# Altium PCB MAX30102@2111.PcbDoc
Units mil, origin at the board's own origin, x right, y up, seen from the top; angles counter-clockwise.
Board outline 354.33 x 295.28 mil, 2 copper layers (Top Layer, Bottom Layer); 8 components, 6 nets, 42 pads, 10 vias.
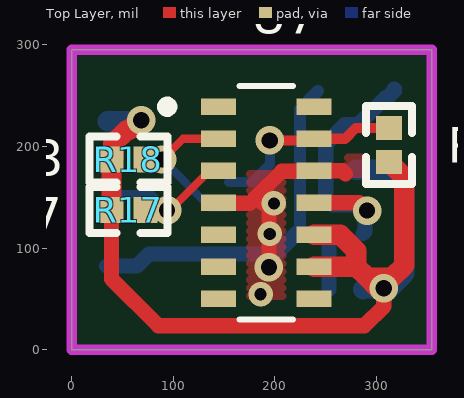
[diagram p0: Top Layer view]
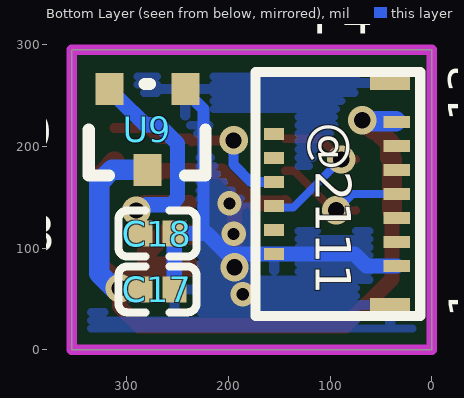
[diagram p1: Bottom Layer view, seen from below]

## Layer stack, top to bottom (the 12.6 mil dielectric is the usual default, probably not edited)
Top Solder: solder mask 0.4, Solder Resist, Dk 3.5
Top Layer: signal copper 1.4
Dielectric 1: dielectric 12.6, FR-4, Dk 4.8
Bottom Layer: signal copper 1.4
Bottom Solder: solder mask 0.4, Solder Resist, Dk 3.5

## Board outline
0,0 354.33,0 354.33,295.28 0,295.28

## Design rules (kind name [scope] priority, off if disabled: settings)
Clearance Clearance_1 [InPolygon] p1: gap=10 ignorepadtopadclearanceinfootprint=FALSE
Clearance [All] p2: gap=6 ignorepadtopadclearanceinfootprint=FALSE
ComponentClearance [All] p1 off: gap=10 collisioncheckmode=3 verticalgap=10 showdistances=FALSE
DiffPairsRouting [All] p1: maxlimit=10 minlimit=7 mostfreqgap=8 toplayer_minwidth=6 toplayer_maxwidth=15 toplayer_prefwidth=8 bottomlayer_minwidth=6 bottomlayer_maxwidth=15 bottomlayer_prefwidth=8 maxuncoupledlength=500
MinimumSolderMaskSliver [All] p1 off: minsoldermaskwidth=10
PolygonConnect PolygonConnect_1 [IsVia] p1: connectstyle=Direct reliefconductorwidth=10 reliefentries=4 polygonreliefangle="90 Angle" airgapwidth=10
PolygonConnect [All] p2: connectstyle=Relief reliefconductorwidth=10 reliefentries=4 polygonreliefangle="90 Angle" airgapwidth=10
RoutingVias [All] p1: holewidth=16 width=28 viastyle="Through Hole" minholewidth=12 minwidth=24 maxholewidth=28 maxwidth=50
SilkToSilkClearance [All] p1 off: silktosilkclearance=10
SilkToSolderMaskClearance [IsPad] p1 off: minsilkscreentomaskgap=10 clearancetoexposedcopper=TRUE
SolderMaskExpansion [All] p1: expansion=4 istentingtop=FALSE
Width [All] p1: maxlimit=100 minlimit=6 preferedwidth=10
25 further rules are at their usual default settings.

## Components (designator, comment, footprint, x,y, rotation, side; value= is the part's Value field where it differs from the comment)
C17 "100nF" 0402_C 286.76,59.42 r90 bottom
C18 "100nF" 0402_C 286.76,114.33 r90 bottom
P4 "13PIN_0.3mm" FFC/FPC-13(6+7)-P0.3 34.34,153.17 r90 bottom
R16 "10K" 0402 312.08,184.92 r90 top
R17 "10K" 0402 39.1,137.31 r0 top
R18 "10K" 0402 39.1,187.44 r0 top
U7 "MAX30102EFD+T" 21-1048_F143A5+1_MXM-M 191.48,144.64 r0 top
U9 "ME6206A18M3G" SOT-23 242.53,256.52 r0 bottom

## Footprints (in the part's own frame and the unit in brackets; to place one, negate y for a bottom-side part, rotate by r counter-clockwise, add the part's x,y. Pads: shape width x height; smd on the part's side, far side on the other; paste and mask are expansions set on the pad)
21-1048_F143A5+1_MXM-M [mil]
  rect 34x16 smd paste+0 mask+4: 1(-47,94.49) 2(-47,62.99) 3(-47,31.5) 4(-47,0) 5(-47,-31.5) 6(-47,-62.99) 7(-47,-94.49) 8(47,-94.49) 9(47,-62.99) 10(47,-31.5) 11(47,0) 12(47,31.5) 13(47,62.99) 14(47,94.49)
  silkscreen extent -102,-115 26,115
0402 [mm]
  rect 0.6x0.65 smd mask+0.051: 1(0,0) 2(0.85,0)
  silkscreen extent -0.55,-0.58 1.4,0.57
0402_C [mm]
  rect 0.65x0.6 smd mask+0.051: 1(0,0) 2(0,-0.85)
  silkscreen extent -0.58,-1.4 0.57,0.55
FFC/FPC-13(6+7)-P0.3 [mm]
  rect 0.35x1 smd mask+0.102: 0(-2.775,0.165) 0(2.775,0.165)
  rect 0.3x0.67 smd mask+0.102: 1(-1.8,0) 3(-1.2,0) 5(-0.6,0) 7(0,0) 9(0.6,0) 11(1.2,0) 13(1.8,0)
  rect 0.3x0.5 smd mask+0.102: 2(-1.5,3.065) 4(-0.9,3.065) 6(-0.3,3.065) 8(0.3,3.065) 10(0.9,3.065) 12(1.5,3.065)
  silkscreen extent -3.05,-0.59 3.05,3.53
SOT-23 [mm]
  rect 0.7x0.8 smd: 1(0,0) 2(1.9,0) 3(0.95,2.02)
  silkscreen extent -0.51,-0.13 2.41,2.16

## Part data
C17 C18: library part Cap, "Capacitor"
P4: library part "Header 13", "Header, 13-Pin"
R16 R17 R18: library part Res1, "Resistor"
U7: "No Description Available"

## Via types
v1: diameter 28, hole 16, Top Layer to Bottom Layer, tented both sides, 7 vias
v2: diameter 24, hole 12, Top Layer to Bottom Layer, tented both sides, 3 vias

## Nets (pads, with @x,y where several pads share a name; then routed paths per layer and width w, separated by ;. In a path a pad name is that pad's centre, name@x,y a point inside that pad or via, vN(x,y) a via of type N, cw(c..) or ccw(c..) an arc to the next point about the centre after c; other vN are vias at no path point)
+1.8V: C18.1 U7.11 U9.2 | length 269.6
  Top Layer w15: U7.11 283.03,144.64 v1(290.7,136.97)
  Bottom Layer w15: C18.1 288.73,116.3 288.73,135 v1(290.7,136.97) 287.18,136.97 281.52,142.63 256.73,142.63 250.14,149.22 250.14,202.95 268.7,221.52 282.33,221.52 309.09,248.27 311.05,248.27 317.33,254.55 U9.2
+3V3: C17.1 P4.13 R16.1 R17.1 R18.1 U7.9 U7.10 U9.3 | length 1012.3
  Top Layer w15: R17.1 39.1,69.7 85.15,23.64 288.15,23.64 307.17,42.66 v1(307.17,60.55)
  Top Layer w20: R17.1 R18.1 40.91,189.25 40.91,203.02 54.12,216.24 56.48,216.24 66.22,225.98 v1(68.38,225.98) ; U7.9 280.17,81.65 ; U7.10 264.32,113.14 280.17,97.29 280.17,81.65 ; R16.1 313.06,184.92 314.87,183.11 314.87,182.12 327.34,169.66 327.34,82.88 v1@315.55,71.1 ; 280.17,81.65 290.72,71.1 ; 290.72,71.1 v1@315.55,71.1 ; 290.72,71.1 301.27,60.55 v1(307.17,60.55) 307.17,62.71 v1@315.55,71.1
  Bottom Layer w20: P4.13@35.31,225.01 67.41,225.01 v1(68.38,225.98) ; U9.3 314.73,176.99 327.33,164.39 327.33,75.01 312.87,60.55 v1(307.17,60.55) 287.89,60.55 C17.1
GND: C17.2 C18.2 P4.0 P4.1 P4.2 U7.4 U7.12 U9.1 | length 661.4
  Top Layer w15: U7.4 144.98,144.14 175.22,144.14 181.72,150.63 ; v1(194.13,81.21) 194.13,139.13 v2(199,144) 188.35,144 181.72,150.63 ; 269.48,172.89 266.24,176.13 U7.12 237.98,175.63 206.71,175.63 181.72,150.63
  Bottom Layer w8: U9.1@242.53,254.55 U9.1
  Bottom Layer w12: 224.63,114.33 224.63,236.65 U9.1@242.53,254.55
  Bottom Layer w15: P4.1 64.32,82.31 76.13,94.12 P4.2 200.86,94.12 221.07,114.33 C18.2 C17.2
  other v2: 185.94,54.53 195,114
MAX_INT: P4.8 R16.2 U7.13 | length 194
  Top Layer w10: v1(195,206) 234.85,206 235.85,205 U7.13 269.1,207.63 279.85,218.38 R16.2
  Bottom Layer w10: P4.8 177.83,164.98 195,182.15 v1(195,206)
MAX_SCL: P4.6 R18.2 U7.2 | length 164.4
  Top Layer w8: R18.2@74.56,187.44 74.79,187.21 v1(89.17,187.21) 109.59,207.63 U7.2
  Bottom Layer w8: v1(89.17,187.21) 136.33,140.06 153.71,140.06 P4.6
MAX_SDA: P4.7 R17.2 U7.3 | length 152.3
  Top Layer w8: R17.2@74.56,137.31 74.71,137.16 v1(93.88,137.16) 96.5,137.16 135.48,176.13 U7.3
  Bottom Layer w8: P4.7 77.86,153.17 v1(93.88,137.16)
pads on no net: P4.3 P4.4 P4.5 P4.9 P4.10 P4.11 P4.12 U7.1 U7.5 U7.6 U7.7 U7.8 U7.14

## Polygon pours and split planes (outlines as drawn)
GND on Top Layer "GND" (hatched Horizontal grid 8 track 8, remove dead copper, pour order 0): 0,295.28 354.33,295.28 354.33,0 0,0
GND on Bottom Layer "GND" (hatched Horizontal grid 8 track 8, remove dead copper, pour order 1): 0,295.28 0,0 354.33,0 354.33,295.28

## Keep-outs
Keep-Out Layer:
  the board outline again, w10

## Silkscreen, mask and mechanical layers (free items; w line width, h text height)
Bottom Overlay:
  text "@2111" at 114.15,223.98 h35 r90
Mechanical 1:
  the board outline again, w10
